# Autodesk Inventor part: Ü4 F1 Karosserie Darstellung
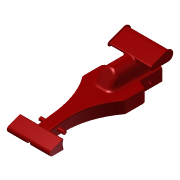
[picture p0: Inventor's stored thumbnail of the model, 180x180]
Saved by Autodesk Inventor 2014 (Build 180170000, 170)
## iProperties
Created: 2013-07
Part Number: Ü4 F1 Karosserie Darstellung
Material: Generisch
Document SubType Name: Modeling
Designer: Sofia
Density: 1 g/cm^3
Appearance: Rot
Author: Sofia
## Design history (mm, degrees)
sketch "Skizze1"
  geometry: L1 (0, 0)-(200, 0); L2 (200, 0)-(200, 20); L3 (200, 20)-(110, 20); L4 (0, 8)-(0, 0); A1 r 510.167 centre (110, -490.167) between (110, 20) and (0, 8)
  constraints: 8 end point, 2 perpendicular, 2 point on circle, 1 centre point, 1 horizontal, 1 parallel, 1 tangent
  dimensions: "d2" = 200 distance of L1.start L1.end; "d3" = 20 distance of L1.end L2.end; "d4" = 90 distance of L2.end L3.end; "d5" = 8 distance of L4.start L1.start
extrude "Extrusion1" new body sketch "Skizze1" distance "d6" = 35; taper "d7" = 0 deg
sketch "Skizze2"
  geometry: L1 (0, 0)-(200, 0) reference; L2 (0, 35)-(200, 35) reference; L3 (0, 0)-(0, 35) reference; L4 (0, 10)-(50, 10); L5 (200, 35)-(160, 35); L6 (160, 35)-(160, 19); L7 (160, 19)-(200, 19); L8 (200, 19)-(200, 35); A1 r 120 centre (50, 130) between (50, 10) and (123.314, 35)
  constraints: 10 end point, 2 parallel, 2 perpendicular, 2 point on circle, 2 point on line, 1 centre point, 1 horizontal, 1 tangent
  dimensions: "d8" = 50 distance of L4.start L4.end; "d9" = 10 distance between parallel lines of L4 L1; "d10" = 120 radius of A1; "d13" = 40 distance of L7.end L6.end; "d14" = 16 distance of L6.end L5.end
extrude "Extrusion2" cut sketch "Skizze2" stored distance "d15" = 35; taper "d16" = 0 deg
sketch "Skizze3"
  geometry: L1 (0, 0)-(0, 8) reference; L2 (50, 0)-(0, 0) reference; C1 r 3 at (40, 8)
  constraints: 1 centre point
  dimensions: "d17" = 6 diameter of C1; "d18" = 8 distance from line of C1.centre L2; "d19" = 40 distance from line of C1.centre L1
extrude "Extrusion3" join sketch "Skizze3" distance "d20" = 10; taper "d21" = 0 deg
hole "Bohrung1" diameter "d24" = 3; stored, may be unused: countersink angle "d28" = 90 deg, drill point angle "d30" = 118 deg; dims "d22" = 10, "d23" = 10, "d25" = 6, "d26" = 4, "d27" = 2, "d29" = 8
pattern_linear "Rechteckige Anordnung1"
fillet "Rundung1" dims "d34" = 8
mirror "Spiegeln1"
sketch "Skizze4"
  geometry: L1 (38, 0)-(0, 0) reference; L2 (38, 20)-(0, 20) reference; L3 (5, 20)-(5, 30); L4 (33, 30)-(33, 20); A1 r 14 centre (19, 30) between (33, 30) and (5, 30); 2 further points
  constraints: 4 end point, 2 perpendicular, 2 point on circle, 2 point on line, 2 tangent, 1 centre point, 1 midpoint, 1 vertical alignment
  dimensions: "d35" = 14 radius of A1; "d36" = 30 distance from line of A1.centre L1
extrude "Extrusion4" join sketch "Skizze4" distance "d37" = 80; taper "d38" = 0 deg
sketch "Skizze5"
  geometry: L1 (200, 0)-(0, 0) reference; L2 (0, 0)-(0, 8) reference; L3 (110, 20)-(120, 20) reference; L4 (120, 20)-(120, 44) reference; L5 (120, 44)-(200, 44) reference; L6 (200, 44)-(200, 0) reference; L7 (25.066, 17.123)-(0, 8); L8 (168.592, 41)-(193.592, 41); L9 (191.4, 53.43)-(167.908, 44.879); C1 r 1.5 at (180, 8) reference; C2 r 1.5 at (40, 8) reference; A1 r 510.167 centre (110, -490.167) between (110, 20) and (0, 8) reference; A2 r 17.5 centre (40, 8) between (25.066, 17.123) and (24.436, 0); A3 r 6.408 centre (193.592, 47.408) between (193.592, 41) and (191.4, 53.43); A4 r 2 centre (168.592, 43) between (167.908, 44.879) and (168.592, 41)
  constraints: 6 end point, 6 point on circle, 5 tangent, 3 centre point, 1 coincident, 1 perpendicular, 1 point on line
  dimensions: "d39" = 17.5 radius of A2; "d40" = 20 deg angle of L1 L7; "d41" = 20 deg angle of L8 L9; "d42" = 2 radius of A4; "d43" = 25 distance of L8.start L8.end; "d44" = 3 distance between parallel lines of L5 L8
  node "Schnittkanten projizieren1"
extrude "Extrusion5" join sketch "Skizze5" stored distance "d45" = 70; taper "d46" = 0 deg
extrude "Extrusion6" join sketch "Skizze5" stored distance "d47" = 70; taper "d48" = 0 deg
hole "Bohrung2" diameter "d51" = 19.5; stored, may be unused: countersink angle "d55" = 90 deg, drill point angle "d57" = 118 deg; dims "d49" = 10, "d50" = 10, "d52" = 6, "d53" = 4, "d54" = 2, "d56" = 55
sketch "Skizze6"
  geometry: L1 (200, 0)-(0, 0) reference; L2 (0, 0)-(0, 8) reference; L3 (0, 8)-(25.066, 17.123) reference; L4 (110, 20)-(120, 20) reference; L5 (120, 20)-(120, 44) reference; L6 (120, 44)-(166.86, 44) reference; L7 (167.908, 44.879)-(191.4, 53.43) reference; L8 (199.019, 44)-(200, 44) reference; L9 (200, 44)-(200, 39.75) reference; L10 (200, 39.75)-(145, 39.75) reference; L11 (145, 39.75)-(139.142, 30) reference; L12 (139.142, 30)-(145, 20.25) reference; L13 (145, 20.25)-(200, 20.25) reference; L14 (200, 20.25)-(200, 0) reference; L15 (120, 20)-(133.856, 44); C1 r 1.5 at (180, 8) reference; C2 r 1.5 at (40, 8) reference; A1 r 17.5 centre (40, 8) between (25.066, 17.123) and (23.1, 12.544) reference; A2 r 510.167 centre (110, -490.167) between (110, 20) and (23.1, 12.544) reference; A3 r 2 centre (168.592, 43) between (167.908, 44.879) and (166.86, 44) reference; A4 r 6.408 centre (193.592, 47.408) between (199.019, 44) and (191.4, 53.43) reference
  constraints: 2 end point, 1 point on line
  dimensions: "d58" = 30 deg angle of L5 L15
extrude "Extrusion7" cut sketch "Skizze6" stored distance "d59" = 10; taper "d60" = 0 deg
sketch "Skizze7"
  geometry: L1 (168.592, 41)-(193.592, 41) reference; L2 (191.4, 53.43)-(167.908, 44.879) reference; L3 (167.224, 46.759)-(190.716, 55.309); L4 (193.592, 39)-(168.592, 39); A1 r 6.408 centre (193.592, 47.408) between (193.592, 41) and (191.4, 53.43) reference; A2 r 2 centre (168.592, 43) between (167.908, 44.879) and (168.592, 41) reference; A3 r 8.408 centre (193.592, 47.408) between (193.592, 39) and (190.716, 55.309); A4 r 4 centre (168.592, 43) between (167.224, 46.759) and (168.592, 39); 1 further point
  constraints: 4 end point, 4 point on circle, 2 centre point, 3 other
  dimensions: "d61" = 2 distance between parallel lines of L3 L2
extrude "Extrusion8" join sketch "Skizze7" distance "d62" = 1; taper "d63" = 0 deg
mirror "Spiegeln2"
fillet "Rundung2"
fillet "Rundung3" dims "d64" = 2
fillet "Rundung4" dims "d65" = 7
sketch "Skizze8"
  geometry: L1 (38, 0)-(0, 0) reference; L2 (16, 6)-(22, 6); L3 (22, 6)-(22, 0); L4 (22, 0)-(16, 0); L5 (16, 0)-(16, 6); 2 further points
  constraints: 8 end point, 2 midpoint, 2 parallel, 1 horizontal, 1 perpendicular
  dimensions: "d66" = 6 distance of L3.end L4.end; "d67" = 6 distance of L2.end L3.end
extrude "Extrusion9" cut sketch "Skizze8" stored distance "d68" = 1; taper "d69" = 0 deg
node "Volumenkörper1"
node "Schnittkanten projizieren2"
